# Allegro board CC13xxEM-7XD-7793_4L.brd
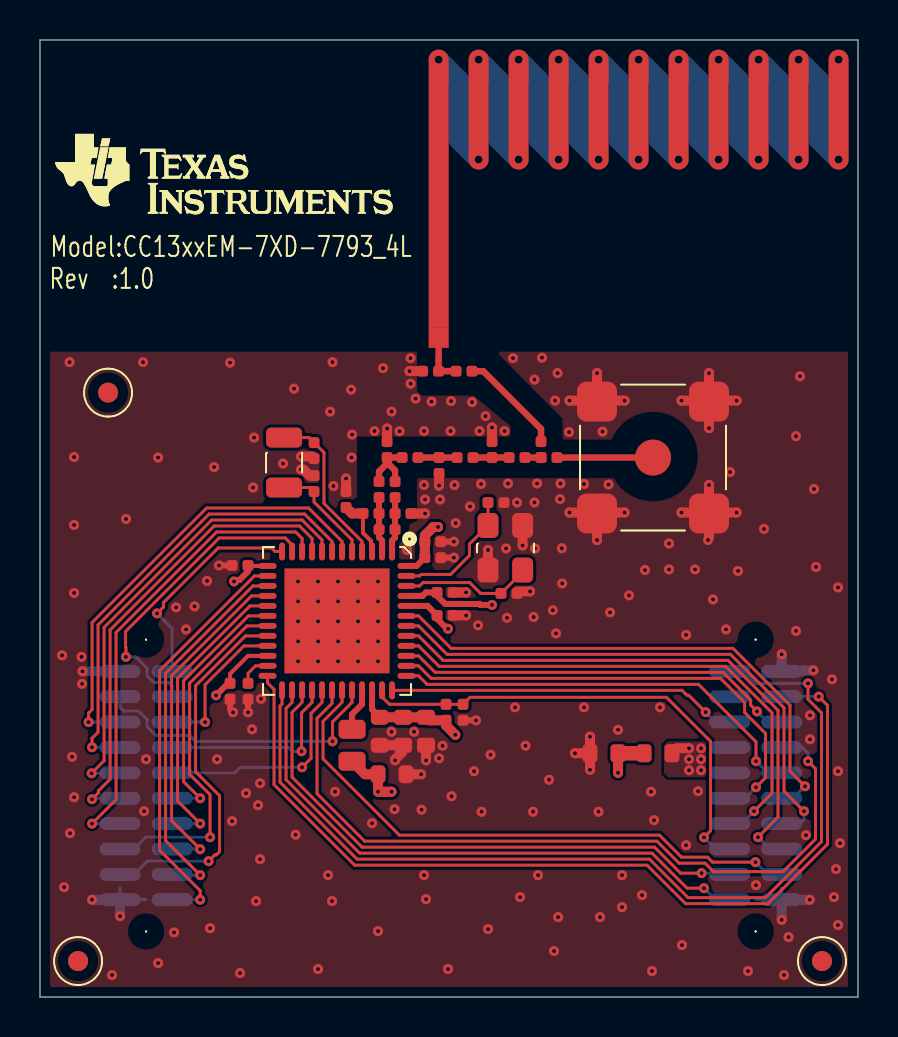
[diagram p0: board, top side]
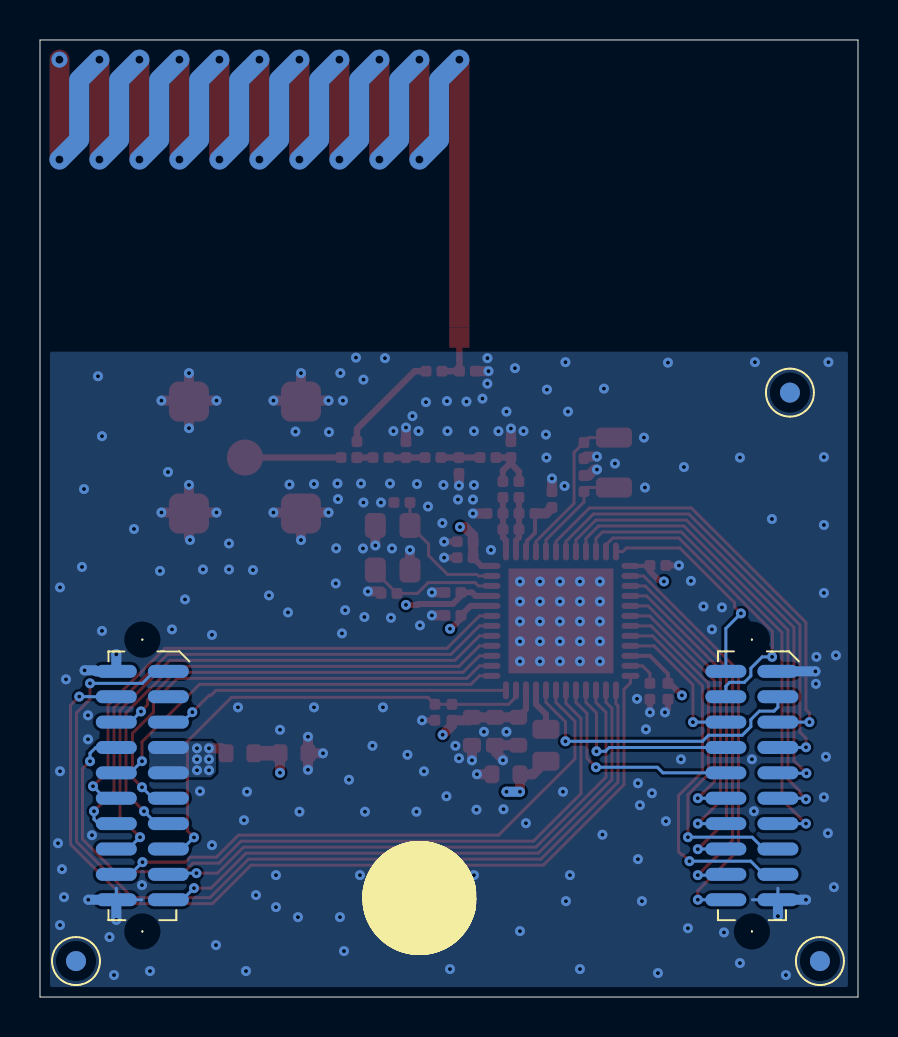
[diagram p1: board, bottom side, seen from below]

Outline 40.9 x 47.9 mm; copper layers: TOP, L2, L3, BOTTOM. Coordinates in mm from the lower left corner of the outline.
Outline path: 0,47.9 0,0 40.9,0 40.9,47.9 0,47.9

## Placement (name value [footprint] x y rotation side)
A1  Antenna PCB helix 868/915MHz  [ANTENNA868_915MHZ_A2N]  19.93 32.99 0 top
C1  DNM  [CAPC1608X90L]  28.9 12.2 180 top
C11  3.6pF  [CAPC1005X60L]  17.75 24.2 0 top
C12  2.7pF  [CAPC1005X60L]  17.35 27 90 top
C13  6.2pF  [CAPC1005X60L]  19.95 26.2 90 top
C14  3.3pF  [CAPC1005X60L]  22.6 27.8 270 top
C15  100pF  [CAPC1005X60L]  24.25 27 180 top
C21  100pF  [CAPC1005X60L]  15.3 25.3 270 top
C22  3.6pF  [CAPC1005X60L]  16.95 25 90 top
C41  12pF  [CAPC1005X60L]  13.7 27.75 270 top
C51  12pF  [CAPC1005X60L]  13.7 25.3 90 top
C131  100nF  [CAPC1005X60L]  10.4 21.6 180 top
C221  100nF  [CAPC1005X60L]  9.5 15.7 270 top
C231  1uF  [CAPC1005X60L]  10.4 15.7 270 top
C331  22uF  [CAPC1608X100A2L]  16.9 11.15 0 top
C341  22uF  [CAPC1608X100A2L]  16.99 14 270 top
C342  100nF  [CAPC1608X90L]  18.15 14 270 top
C343  NC  [CAPC1608X90L]  19.3 14 270 top
C351  100nF  [CAPC1005X60L]  21.15 14.65 270 top
C441  100nF  [CAPC1005X60L]  19.85 19.1 0 top
C451  100nF  [CAPC1005X60L]  19.85 20.25 0 top
C461  DNM  [CAPC1005X60L]  23.05 20.2 0 top
C471  DNM  [CAPC1005X60L]  22.4 24.75 0 top
C481  100nF  [CAPC1005X60L]  19.24 21.99 0 top
C482  DNM  [CAPC1005X60L]  19.24 22.79 0 top
FIDU1  FIDU_1MM  [FID100X115]  1.9 1.8 0 top
FIDU2  FIDU_1MM  [FID100X115]  39.1 1.8 0 top
FIDU3  FIDU_1MM  [FID100X115]  3.4 30.25 0 top
FIDU4  FIDU_1MM  [FID100X115]  1.9 1.8 180 bottom
FIDU5  FIDU_1MM  [FID100X115]  39.1 1.8 180 bottom
FIDU6  FIDU_1MM  [FID100X115]  3.4 30.25 180 bottom
FL1  BLM18HE152SN1  [FIL_BLM18HE152SN1DL]  30.2 12.2 0 top
J1  SMA-10V21-TGG  [HUSTSAN_SMA10V21TGGAN]  30.65 27 0 top
L11  18nH  [INDC1005X60L]  17.75 23.4 180 top
L12  7.5nH  [INDC1005X60A2L]  17.76 25 90 top
L13  6.8nH  [INDC1005X60L]  18.1 27 0 top
L14  6.8nH  [INDC1005X60L]  20.85 27 0 top
L15  TBD  [INDC1005X60L]  19.93 31.33 180 top
L21  7.5nH  [INDC1005X60A2L]  16.95 24.2 180 top
L331  6.8uH  [INDC2012X150L]  15.6 13.4 270 top
NOREF  -  []  0 40.78 0 top
NOREF#2  -  []  1.75 43.2 0 top
NOREF#3  -  []  32.36 0 90 top
NOREF#4  -  []  25.1 1.92 180 bottom
P1  SFM-110-02-S-D-A-K-TR  [SAMTEC_SFM11002AN]  4 16.3 0 bottom
P2  SFM-110-02-S-D-A-K-TR  [SAMTEC_SFM11002AN]  34.48 16.3 0 bottom
R11  0  [RESC1005X40L]  25.85 27 180 top
R12  DNM  [RESC1005X40L]  25.05 27 90 top
R13  0  [RESC1005X40L]  20.8 31.32 0 top
R351  100k  [RESC1005X40L]  20.3 14.65 270 top
U1  CC13xx 7x7  [QFNFC50P700X700X80-49CN]  17.6 22.3 180 top
Y1  32.768kHz  [XTAL_FC-135N]  12.2 28 270 top
Y2  24MHz  [OSCCC250X320X60-4L]  22.4 23.6 270 top

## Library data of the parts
A1 = ANTENNA: User Part Number: #PN
C1 C342 C343 = CAPACITOR: alternate symbols: (CAPC1608X90L,CAPC1608X90M)
C11-C15 C21 C22 C41 C51 C131 C221 C231 C351 C441 C451 C461 C471 C481 C482 = CAPACITOR: alternate symbols: (CAPC1005X60L,CAPC1005X60M)
C331 C341 = CAPACITOR: User Part Number: #PN; alternate symbols: (CAPC1608X100A2L,CAPC1608X100A2M)
FIDU1-FIDU6 = FIDMARK
FL1 = FILTER_2PIN: alternate symbols: (FIL_BLM18HE152SN1DL,FIL_BLM18HE152SN1DM)
J1 = CONN_COAX_1+4: alternate symbols: (HUSTSAN_SMA10V21TGGL,HUSTSAN_SMA10V21TGGM)
L11 L13 L14 = INDUCTOR: alternate symbols: (INDC1005X60L,INDC1005X60M)
L12 L21 = IND_HOR: User Part Number: #PN; alternate symbols: (INDC1005X60A2L,INDC1005X60A2M)
L15 = INDUCTOR: alternate symbols: (INDC1005X60M,INDC1005X60L)
L331 = INDUCTOR: alternate symbols: (INDC2012X150L,INDC2012X150M)
P1 P2 = CONN_HEADER_2X10_P_S
R11-R13 R351 = RESISTOR: alternate symbols: (RESC1005X40L,RESC1005X40M)
U1 = IC_RF_CC13XX_7X7_QFN48_V2: alternate symbols: (QFNFC50P700X700X80-49CL,QFNFC50P700X700X80-49CM)
Y1 = CRYSTAL: alternate symbols: (XTAL_FC-135L,XTAL_FC-135M)
Y2 = XTAL_4PIN_S: alternate symbols: (OSCCC250X320X60-4L,OSCCC250X320X60-4M)

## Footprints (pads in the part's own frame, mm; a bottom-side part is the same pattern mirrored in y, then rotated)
ANTENNA868_915MHZ_A2N
  rect 1x1 smd: 1(0,0)
CAPC1005X60L
  custom 0.135x0.135 smd: 1(0,0) 2(0.8,0)
CAPC1608X90L
  custom 0.188x0.188 smd: 1(0,0) 2(1.4,0)
CAPC1608X100A2L
  custom 0.188x0.188 smd: 1(0,0) 2(1.4,0)
FID100X115
  oval 1x1 smd: 1(0,0)
FIL_BLM18HE152SN1DL
  custom 0.188x0.188 smd: 1(0,0) 2(1.4,0)
HUSTSAN_SMA10V21TGGAN
  round 1.801 smd: 1(0,0)
  custom 0.5x0.5 smd: 2(-2.8,-2.8) 3(2.8,-2.8) 4(2.8,2.8) 5(-2.8,2.8)
INDC1005X60A2L
  custom 0.135x0.135 smd: 1(0,0) 2(0.8,0)
INDC1005X60L
  custom 0.135x0.135 smd: 1(0,0) 2(0.8,0)
INDC2012X150L
  custom 0.237x0.237 smd: 1(0,0) 2(1.6,0)
OSCCC250X320X60-4L
  custom 0.263x0.263 smd: 1(0,0) 2(2.23,0) 3(2.23,1.73) 4(0,1.73)
QFNFC50P700X700X80-49CN
  oval 0.3x0.9 smd: 1(0,0) 2(0.5,0) 3(1,0) 4(1.5,0) 5(2,0) 6(2.5,0) 7(3,0) 8(3.5,0) 9(4,0) 10(4.5,0) 11(5,0) 12(5.5,0) 25(5.5,6.95) 26(5,6.95) 27(4.5,6.95) 28(4,6.95) 29(3.5,6.95) 30(3,6.95) 31(2.5,6.95) 32(2,6.95) 33(1.5,6.95) 34(1,6.95) 35(0.5,6.95) 36(0,6.95)
  oval 0.9x0.3 smd: 13(6.225,0.725) 14(6.225,1.225) 15(6.225,1.725) 16(6.225,2.225) 17(6.225,2.725) 18(6.225,3.225) 19(6.225,3.725) 20(6.225,4.225) 21(6.225,4.725) 22(6.225,5.225) 23(6.225,5.725) 24(6.225,6.225) 37(-0.725,6.225) 38(-0.725,5.725) 39(-0.725,5.225) 40(-0.725,4.725) 41(-0.725,4.225) 42(-0.725,3.725) 43(-0.725,3.225) 44(-0.725,2.725) 45(-0.725,2.225) 46(-0.725,1.725) 47(-0.725,1.225) 48(-0.725,0.725)
  rect 5.25x5.25 smd: 49(2.75,3.475)
RESC1005X40L
  custom 0.135x0.135 smd: 1(0,0) 2(0.8,0)
SAMTEC_SFM11002AN
  round 0.099 hole 1.501 unplated: (1.302,-1.588) (1.302,13.017)
  oval 2.05x0.65 smd: 1(0,0) 2(2.604,0) 3(0,1.27) 4(2.604,1.27) 5(0,2.54) 6(2.604,2.54) 7(0,3.81) 8(2.604,3.81) 9(0,5.08) 10(2.604,5.08) 11(0,6.35) 12(2.604,6.35) 13(0,7.62) 14(2.604,7.62) 15(0,8.89) 16(2.604,8.89) 17(0,10.16) 18(2.604,10.16) 19(0,11.43) 20(2.604,11.43)
XTAL_FC-135N
  custom 0.25x0.25 smd: 1(0,0) 2(2.5,0)

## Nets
GND: C1.2 C11.2 C12.2 C13.1 C14.1 C21.1 C41.2 C51.2 C131.2 C221.2 C231.2 C331.2 C341.2 C342.2 C343.2 C351.2 C441.2 C451.2 C461.2 C471.2 C481.2 C482.2 J1.2 J1.3 J1.4 J1.5 L15.2 P1.1 P1.19 P2.2 P2.20 U1.49(VSS) Y2.2 Y2.4
VDD_EB: FL1.2 P2.7 P2.9
VDDR: C331.1 C451.1 C481.1 C482.1 L331.2 U1.45(VDDR#45) U1.48(VDDR#48)
VDDS: C1.1 C131.1 C221.1 C341.1 C342.1 C343.1 C441.1 FL1.1 R351.2 U1.13(VDDS2) U1.22(VDDS3) U1.34(VDDS_DCDC) U1.44(VDDS)
DCDC_SW: L331.1 U1.33(DCDC_SW)
DIO_1: P1.5 U1.6(DIO_1)
DIO_2: P1.7 U1.7(DIO_2)
DIO_3: P1.9 U1.8(DIO_3)
DIO_4: P1.11 U1.9(DIO_4)
DIO_5: P1.13 U1.10(DIO_5)
DIO_6: P1.4 U1.11(DIO_6)
DIO_7: P1.2 U1.12(DIO_7)
DIO_8: P1.20 U1.14(DIO_8)
DIO_9: P1.18 U1.15(DIO_9)
DIO_10: P1.16 U1.16(DIO_10)
DIO_11: P1.14 U1.17(DIO_11)
DIO_12: P1.12 U1.18(DIO_12)
DIO_13: P1.15 U1.19(DIO_13)
DIO_14: P1.17 U1.20(DIO_14)
DIO_15: P1.6 U1.21(DIO_15)
DIO_16 / JTAG TDO: P2.19 U1.26(DIO_16)
DIO_17 / JTAG TDI: P2.17 U1.27(DIO_17)
DIO_18: P1.8 U1.28(DIO_18)
DIO_19: P1.10 U1.29(DIO_19)
DIO_20: P2.8 U1.30(DIO_20)
DIO_21: P2.18 U1.31(DIO_21)
DIO_22: P1.3 U1.32(DIO_22)
DIO_23: P2.5 U1.36(DIO_23)
DIO_24: P2.10 U1.37(DIO_24)
DIO_25: P2.11 U1.38(DIO_25)
DIO_26: P2.6 U1.39(DIO_26)
DIO_27: P2.13 U1.40(DIO_27)
DIO_28: P2.16 U1.41(DIO_28)
DIO_29: P2.14 U1.42(DIO_29)
DIO_30: P2.12 U1.43(DIO_30)
JTAG_TCK: P2.1 U1.25(JTAG_TCKC)
JTAG_TMS: P2.4 U1.24(JTAG_TMSC)
NRESET: C351.1 P2.15 R351.1 U1.35(RESET_N)
N485531: J1.1 R11.1
N485535: A1.1(FEED/GND_1) L15.1 R13.1
N485571: C461.1 U1.46(X24M_N) Y2.3
N485643: C22.1 L11.2 L21.1 U1.2(RF_N)
N485645: C11.1 L11.1 L12.1 U1.1(RF_P)
N485661: C12.1 C22.2 L12.2 L13.1
N485675: C13.2 L13.2 L14.1
N485699: C231.1 U1.23(DCOUPL)
N485701: C41.1 U1.4(X32K_Q1) Y1.1
N485707: C51.1 U1.5(X32K_Q2) Y1.2
N485827: C14.2 C15.2 L14.2
N485893: C15.1 R11.2 R12.1
N485901: R12.2 R13.2
N485927: C21.2 L21.2 U1.3(RX_TX)
N485953: C471.1 U1.47(X24M_P) Y2.1

Pads without a net: FIDU1 1; FIDU2 1; FIDU3 1; FIDU4 1; FIDU5 1; FIDU6 1; P2 3

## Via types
v1: diameter 0.5, hole 0.2, TOP to BOTTOM, 286 vias
v2: diameter 0.8, hole 0.4, TOP to BOTTOM, 21 vias

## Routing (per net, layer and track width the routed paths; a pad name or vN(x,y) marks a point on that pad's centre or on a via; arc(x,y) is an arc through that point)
GND: length 51.4
  TOP w0.15: v1(14.9,18.8) 14.88,18.83 U1.49
  TOP w0.3: C131.2 v1(8.95,21.6) ; v1(20.7,22.79) C482.2 ; C221.2 9.5,14.4 9.65,14.25 v1(9.65,14.25) ; v1(20.7,21.99) C481.2 ; v1(10.4,14.25) C231.2 ; C351.2 v1(21.8,13.85)
  TOP w0.5: C11.2 v1(19.26,24.2) ; C1.2 v1(27.5,13.03) ; C1.2 v1(26.75,12.2) ; C1.2 v1(27.5,11.37) ; v1(34.83,29.85) 33.45,29.85 ; 33.45,29.85 J1.4 v1(33.45,28.47) ; 33.45,29.85 v1(32.08,29.85) ; 33.45,29.85 v1(33.45,31.23) ; 33.45,24.25 v1(32.08,24.25) ; 33.45,24.25 v1(34.83,24.25) ; 33.45,24.25 v1(33.45,25.63) ; 33.45,24.25 J1.3 33.45,23 ; L15.2 v1(18.48,31.33) ; C12.2 17.35,28.45 v1(17.36,28.45) ; v1(19.3,11.85) C343.2 ; 22.4,21.47 v1(22.4,22.37) ; v1(13.06,27.05) 13.6,27.05 C41.2 ; C441.2 v1(21.31,19.1) ; v1(27.85,22.87) J1.2 27.85,24.25 ; v1(17.75,11.85) 17.75,11.9 18.1,12.25 18.1,12.4 18.15,12.45 C342.2 17.1,12.6 ; v1(13.05,26.4) 13.18,26.4 13.48,26.1 C51.2 ; v1(24.13,22.6) Y2.4 24.13,23.7 ; C14.1 v1(22.6,28.5) ; 23.85,20.3 v1(24.51,20.3) ; C13.1 v1(19.95,25.6) ; 27.85,29.85 v1(26.48,29.85) ; 27.85,29.85 v1(27.85,31.23) ; 27.85,29.85 v1(29.23,29.85) ; 27.85,24.25 v1(26.48,24.25) ; 27.85,24.25 v1(29.23,24.25) ; C21.1 v1(15.3,25.95) ; C451.2 v1(21.31,20.25) ; C331.2 v1(19.06,11.15)
  BOTTOM w0.15: 38.08,16.3 38.36,16.3 ; 37.09,5.45 P2.20 35.81,4.87 ; 5.28,4.87 P1.19 4,5.45
  BOTTOM w0.5: v1(37.09,3.87) P2.20 v1(38.49,4.87) ; v1(4,4.05) P1.19 v1(2.6,4.87) ; v1(37.09,17.15) P2.2 38.08,16.3 38.13,16.35 v1(38.67,16.35) ; P1.1 v1(2.13,16.3)
  vias: v1(1.1,17.1) v1(1.2,5.5) v1(1.48,31.77) v1(1.5,8.2) v1(1.6,12.02) v1(1.7,27.02) v1(1.7,23.62) v1(1.7,20.22) v1(1.7,10) v1(2.08,17.02) v1(2.1,15.67) v1(3.6,1.1) v1(4.3,23.92) v1(5.15,31.77) v1(5.2,9.3) v1(5.3,11.9) v1(5.9,27) v1(5.9,1.7) v1(6.7,3.23) v1(6.8,19.5) v1(7.3,18.4) v1(7.73,19.55) v1(8.35,20.83) v1(8.5,3.44) v1(8.7,26.52) v1(8.85,11.9) v1(9.5,31.75) v1(9.6,8.8) v1(10,1.2) v1(10.3,10.2) v1(10.6,13.4) v1(10.7,28) v1(10.65,25.5) v1(10.8,4.8) v1(10.9,9.6) v1(11.05,14.92) v1(11,10.7) v1(11,6.9) v1(12.15,26.7) v1(12.7,30.45) v1(12.78,8.12) v1(12.9,20.8) v1(12.9,19.8) v1(12.9,18.8) v1(12.9,17.8) v1(12.9,16.8) v1(13.9,20.8) v1(13.9,19.8) v1(13.9,18.8) v1(13.9,17.8) v1(13.9,16.8) v1(13.9,1.4) v1(14.4,6.1) v1(14.5,29.3) v1(14.63,31.77) v1(14.6,4.8) v1(14.67,25.58) v1(14.75,10.27) v1(14.9,20.8) v1(14.9,19.8) v1(14.9,17.8) v1(14.9,16.8) v1(15.55,30.4) v1(15.6,28.15) v1(15.58,27) v1(15.9,20.8) v1(15.9,19.8) v1(15.9,18.8) v1(15.9,17.8) v1(15.9,16.8) v1(16.6,8.7) v1(16.73,28.33) v1(16.9,20.8) v1(16.9,19.8) v1(16.9,18.8) v1(16.9,17.8) v1(16.9,16.8) v1(16.9,3.3) v1(17.15,31.47) v1(17.58,29.3) v1(17.58,13.27) v1(17.73,9.4) v1(17.98,28.32) v1(18.35,22.38) v1(18.53,31.97) v1(18.53,30.7) v1(18.7,13.27) v1(18.78,29.95) v1(19.08,9.38) v1(19.2,28.33) v1(19.2,25.62) v1(19.25,24.9) v1(19.2,6.1) v1(19.3,4.9) v1(19.58,29.8) v1(20,24.9) v1(19.95,11.95) v1(20.13,12.58) v1(20.4,1.4) v1(20.55,29.83) v1(20.53,28.33) v1(20.58,10.05) v1(20.73,25.62) v1(20.78,23.72) v1(21.5,24.55) v1(21.6,29.77) v1(21.7,11.3) v1(21.9,18.6) v1(21.98,28.33) v1(22.05,25.67) v1(22.08,9.27) v1(22.28,29.08) v1(22.4,3.4) v1(22.53,12.12) v1(23.23,28.33) v1(23.3,22.45) v1(23.35,18.98) v1(23.4,25.7) v1(23.65,31.97) v1(23.75,14.5) v1(23.86,24.75) v1(24,5) v1(24.28,12.58) v1(24.73,30.9) v1(24.73,24.75) v1(24.68,19.02) v1(24.65,9.27) v1(24.85,25.7) v1(24.75,22.45) v1(24.9,6.1) v1(25.1,32) v1(25.45,10.88) v1(25.64,19.36) v1(25.7,2.3) v1(25.75,29.85) v1(25.8,18.2) v1(25.88,31.23) v1(25.9,4) v1(26.03,25.7) v1(26,24.92) v1(26.09,22.46) v1(26.11,20.7) v1(26.45,28.27) v1(27.2,25.67) v1(27.2,14.5) v1(27.93,9.27) v1(28,4) v1(28.13,28.3) v1(28.43,25.65) v1(28.5,19.25) v1(28.9,13.38) v1(29.1,6.1) v1(29.1,4.5) v1(29.45,20.1) v1(30.1,5.1) v1(30.25,21.37) v1(30.55,10.27) v1(30.6,1.3) v1(30.7,8.85) v1(31,14.5) v1(31.45,22.7) v1(31.45,21.4) v1(32.1,2.6) v1(32.3,18.12) v1(32.3,7.6) v1(32.75,21.4) v1(32.9,10.3) v1(33.4,22.87) v1(33.65,19.9) v1(34.3,18.4) v1(34.5,26.27) v1(34.9,21.33) v1(35.4,1.3) v1(35.8,5.6) v1(36.2,23.42) v1(37.2,1.1) v1(37.43,3) v1(37.8,28.07) v1(37.8,18.33) v1(38,31.07) v1(38.3,8.1) v1(38.5,14.1) v1(38.5,12.9) v1(38.7,25.42) v1(38.8,21.52) v1(39.6,15.9) v1(39.7,5) v1(39.8,6.4) v1(39.9,20.5) v1(39.9,11.3) v1(39.9,3.6) v1(40,7.7)
VDD_EB: length 1
  TOP w0.5: FL1.2 31.85,12.45 v1(32.45,12.45)
  vias: v1(32.45,11.9) v1(32.45,11.35) v1(33.05,12.45) v1(33.05,11.9) v1(33.05,11.35)
VDDR: length 30.7
  TOP w0.3: U1.45 19.13,20.08 19.3,20.25 C451.1 19.85,20.08 20.26,19.67 21.98,19.67 ; v1(22.6,19.62) 22.03,19.62 ; U1.48 18.83,21.58 C481.1
  TOP w0.32: 22.03,19.62 21.98,19.67
  TOP w0.5: v1(19.9,23.52) 19.67,23.52 19.24,23.1 C482.1 C481.1 ; L331.2 16.25,11.15 C331.1 v1(16.9,10.27) v1(17.58,10.27)
  L2 w0.5: v1(16.9,10.27) v1(17.58,10.27)
  L3 w0.5: v1(19.9,23.52) 19.9,21.86 20.43,21.34 21.14,21.34 22.6,19.87 v1(22.6,19.62) 22.6,13.64 19.23,10.27 v1(17.58,10.27) v1(16.9,10.27)
  BOTTOM w0.5: v1(16.9,10.27) v1(17.58,10.27)
VDDS: length 65.9
  TOP w0.2: C131.1 10.43,21.58 U1.13 ; C221.1 9.5,16.18 10.4,17.08 U1.22
  TOP w0.3: U1.34 16.6,14.4 16.99,14.01 C341.1 ; v1(20.4,18.43) 20.28,18.55 20.23,18.55 19.85,18.93 C441.1 19.38,19.58 U1.44 ; C221.1 9.41,15.7 v1(8.8,15.1) ; C131.1 10.4,21.3 9.98,20.87 9.78,20.87 v1(9.7,20.8)
  TOP w0.5: v1(28.9,11.22) C1.1 ; C341.1 18.15,14 C342.1 C343.1 19.45,13.85 R351.2 20.3,13.59 v1(20.77,13.12)
  TOP w0.73: FL1.1 C1.1
  L3 w0.5: 16.41,14.44 v1(20.4,18.43) ; 16.41,14.44 15.95,13.98 15.95,7.98 ; 16.41,14.44 19.45,14.44 v1(20.77,13.12) ; 15.95,7.98 15,7.98 8.8,14.18 v1(8.8,15.1) 8.8,19.9 v1(9.7,20.8) ; 15.95,7.98 27.55,7.98 28.9,9.33 v1(28.9,11.22)
DCDC_SW: length 2.2
  TOP w0.3: U1.33 16.1,14.65 15.6,14.15 L331.1
DIO_1: length 22.7
  TOP w0.15: U1.6 15.1,22.8 13.43,24.47 8.33,24.47 2.6,18.75 2.6,14.39 2.43,14.21 v1(2.43,13.76)
  BOTTOM w0.15: v1(2.43,13.76) P1.5
DIO_2: length 22.7
  TOP w0.15: U1.7 14.6,22.8 13.23,24.17 8.46,24.17 2.9,18.62 2.9,13.25 2.6,12.95 v1(2.6,12.5)
  BOTTOM w0.15: v1(2.6,12.5) 2.8,12.5 2.81,12.49 P1.7
DIO_3: length 23.1
  TOP w0.15: U1.8 14.1,22.88 13.1,23.88 8.58,23.88 3.2,18.5 3.2,11.83 v1(2.58,11.2)
  BOTTOM w0.15: P1.9 3.98,11.2 v1(2.58,11.2)
DIO_4: length 23.4
  TOP w0.15: v1(2.6,9.9) 2.92,10.22 2.92,10.32 3.5,10.9 3.5,18.37 8.71,23.58 12.98,23.58 13.6,22.95 U1.9
  BOTTOM w0.15: P1.11 2.7,9.95 2.65,9.9 v1(2.6,9.9)
DIO_5: length 23.6
  TOP w0.15: U1.10 13.1,22.95 12.78,23.27 8.83,23.27 3.8,18.25 3.8,9.88 v1(2.6,8.68)
  BOTTOM w0.15: P1.13 v1(2.6,8.68)
DIO_6: length 15.7
  TOP w0.15: v1(4.3,17.02) 4.3,17.48 4.28,17.49 4.28,18.3 8.96,22.97 12.26,22.97 12.6,22.63 U1.11
  BOTTOM w0.15: v1(4.3,17.02) 4.79,17.02 5.36,16.46 5.36,16.07 5.68,15.75 6.42,15.75 6.61,15.56 P1.4
DIO_7: length 11
  TOP w0.15: v1(5.85,19.2) 6.17,19.52 6.17,19.74 8.91,22.47 11.58,22.47 11.75,22.3 U1.12
  BOTTOM w0.15: P1.2 6.61,18.45 v1(5.85,19.2)
DIO_8: length 21.1
  TOP w0.15: U1.14 10.72,21.08 5.98,16.33 5.98,7.35 8.01,5.32 v1(8.01,4.87)
  BOTTOM w0.15: P1.20 v1(8.01,4.87)
DIO_9: length 19.2
  TOP w0.15: v1(8.01,6.1) 6.28,7.83 6.28,16.21 10.65,20.58 U1.15
  BOTTOM w0.15: v1(8.01,6.1) 6.65,6.1 P1.18
DIO_10: length 17.1
  TOP w0.15: v1(8.01,7.4) 6.58,8.83 6.58,16.08 10.57,20.08 U1.16
  BOTTOM w0.15: P1.16 7.84,7.41 7.84,7.4 v1(8.01,7.4)
DIO_11: length 15.1
  TOP w0.15: U1.17 10.5,19.58 6.88,15.96 6.88,9.81 v1(8.01,8.68)
  BOTTOM w0.15: v1(8.01,8.68) P1.14
DIO_12: length 13.2
  TOP w0.15: U1.18 10.42,19.08 7.18,15.83 7.18,10.78 v1(8.01,9.95)
  BOTTOM w0.15: v1(8.01,9.95) P1.12
DIO_13: length 18
  TOP w0.15: U1.19 10.35,18.58 7.48,15.7 7.48,11.15 8.5,10.13 v1(8.5,8)
  BOTTOM w0.15: v1(8.5,8) 5.29,8 4.7,7.41 P1.15
DIO_14: length 18.9
  TOP w0.15: v1(8.43,6.8) 8.75,7.12 8.82,7.12 8.98,7.27 8.98,10.08 7.78,11.28 7.78,15.58 10.27,18.08 U1.20
  BOTTOM w0.15: P1.17 4.7,6.14 5.36,6.8 v1(8.43,6.8)
DIO_15: length 7.4
  TOP w0.15: U1.21 10.2,17.58 8.25,15.63 v1(8.25,13.76)
  BOTTOM w0.15: P1.6 v1(8.25,13.76)
DIO_16 / JTAG TDO: length 29.3
  TOP w0.15: v1(33.2,5.45) 32.35,5.45 30.6,7.2 15.98,7.2 12.3,10.88 12.3,14.45 12.6,14.75 U1.26
  BOTTOM w0.15: v1(33.2,5.45) 33.78,4.87 P2.19
DIO_17 / JTAG TDI: length 28.4
  TOP w0.15: v1(33.08,6.2) 32.03,6.2 30.73,7.5 16.11,7.5 12.6,11 12.6,14.25 13.1,14.75 U1.27
  BOTTOM w0.15: P2.17 33.78,6.14 33.72,6.2 v1(33.08,6.2)
DIO_18: length 9.8
  TOP w0.15: U1.28 13.6,14.75 13.08,14.22 v1(13.08,12.3)
  BOTTOM w0.15: v1(13.08,12.3) 12.63,12.3 12.44,12.49 P1.8
DIO_19: length 10.9
  TOP w0.15: v1(13.1,11.5) 13.55,11.95 13.55,14.2 14.1,14.75 U1.29
  BOTTOM w0.15: v1(13.1,11.5) 10.03,11.5 9.75,11.22 P1.10
DIO_20: length 38.6
  TOP w0.15: v1(38.4,11.8) 38.78,11.42 38.78,7.9 37.15,6.27 33.68,6.27 33.25,6.7 31.95,6.7 30.85,7.8 16.23,7.8 13.85,10.18 13.85,13.95 14.6,14.7 U1.30
  BOTTOM w0.15: P2.8 38.11,12.49 38.4,12.2 v1(38.4,11.8)
DIO_21: length 29.2
  TOP w0.15: v1(35.78,6.75) 33.63,6.75 33.38,7 32.08,7 30.98,8.1 17.97,8.1 14.15,11.92 14.15,13.8 15.1,14.75 U1.31
  BOTTOM w0.15: P2.18 36.39,6.14 v1(35.78,6.75)
DIO_22: length 15
  TOP w0.15: v1(14.63,12.8) 14.63,13.77 15.6,14.75 U1.32
  BOTTOM w0.15: v1(14.63,12.8) 7.78,12.8 7.48,13.1 5.79,13.1 5.36,13.53 5.36,13.88 4.93,14.31 4.2,14.31 4,14.5 P1.3
DIO_23: length 17.5
  TOP w0.15: v1(33.29,14.26) 32.44,15.1 32.35,15.1 32.1,15.35 U1.36
  BOTTOM w0.15: P2.5 33.78,13.76 v1(33.29,14.26)
DIO_24: length 21.3
  TOP w0.15: U1.37 18.93,16.08 19.36,15.65 32.93,15.65 35.8,12.77 v1(35.8,11.8)
  BOTTOM w0.15: P2.10 36.39,11.22 v1(35.8,11.8)
DIO_25: length 24.1
  TOP w0.15: v1(35.8,10.5) 36.28,10.97 36.28,13.2 35.23,14.24 35.23,14.74 34.03,15.95 19.56,15.95 18.93,16.58 U1.38
  BOTTOM w0.15: P2.11 35.25,9.95 v1(35.8,10.5)
DIO_26: length 20.3
  TOP w0.15: U1.39 18.93,17.08 19.76,16.25 34.15,16.25 35.53,14.87 35.53,14.61 v1(35.85,14.29)
  BOTTOM w0.15: v1(35.85,14.29) 36.39,13.76 P2.6
DIO_27: length 26.4
  TOP w0.15: U1.40 18.93,17.58 19.96,16.55 34.28,16.55 36.6,14.22 36.6,10.2 v1(35.7,9.3)
  BOTTOM w0.15: v1(35.7,9.3) 35.08,8.68 P2.13
DIO_28: length 28.3
  TOP w0.15: U1.41 18.93,18.08 20.16,16.85 34.4,16.85 36.9,14.35 36.9,9 v1(35.9,8)
  BOTTOM w0.15: v1(35.9,8) 36.5,7.4 37.08,7.4 P2.16
DIO_29: length 27.8
  TOP w0.15: v1(38.2,9.3) 37.2,10.3 37.2,14.47 34.53,17.15 20.36,17.15 18.93,18.58 U1.42
  BOTTOM w0.15: v1(38.2,9.3) 38.2,8.9 37.98,8.68 P2.14
DIO_30: length 26.8
  TOP w0.15: U1.43 18.93,19.08 20.56,17.45 34.65,17.45 37.5,14.6 37.5,11.3 v1(38.25,10.55)
  BOTTOM w0.15: v1(38.25,10.55) 37.65,9.95 P2.12
JTAG_TCK: length 47.6
  TOP w0.15: U1.25 12.1,14.67 12,14.57 12,10.75 15.86,6.9 30.48,6.9 32.4,4.97 36.28,4.97 39.08,7.78 39.08,14.22 38.4,14.9 v1(38.4,15.7)
  BOTTOM w0.15: v1(38.4,15.7) 35.78,15.7 35.18,16.3 P2.1
JTAG_TMS: length 46.4
  TOP w0.15: U1.24 11.38,15.72 11.7,15.4 11.7,10.63 15.73,6.6 30.35,6.6 32.28,4.67 36.4,4.67 39.38,7.65 39.38,14.6 v1(38.94,15.04)
  BOTTOM w0.15: v1(38.94,15.04) 38.49,15.04 38.48,15.03 P2.4
Net_62:
  vias: v2(19.93,46.92) v2(21.93,41.92)
Net_63:
  vias: v2(37.93,46.92) v2(39.93,46.92) v2(39.93,41.92)
Net_64:
  vias: v2(35.93,46.92) v2(37.93,41.92)
Net_65:
  vias: v2(33.93,46.92) v2(35.93,41.92)
Net_66:
  vias: v2(31.93,46.92) v2(33.93,41.92)
Net_67:
  vias: v2(29.93,46.92) v2(31.93,41.92)
Net_68:
  vias: v2(27.93,46.92) v2(29.93,41.92)
Net_69:
  vias: v2(25.93,46.92) v2(27.93,41.92)
Net_70:
  vias: v2(23.93,46.92) v2(25.93,41.92)
Net_71:
  vias: v2(21.93,46.92) v2(23.93,41.92)
NRESET: length 24.4
  TOP w0.15: U1.35 17.1,15.02 17.47,14.65 R351.1 C351.1 21.5,15 31.33,15 33.53,12.8 33.53,8.31 v1(33.2,7.99)
  BOTTOM w0.15: v1(33.2,7.99) 33.78,7.41 P2.15
N485531: length 4.8
  TOP w0.32: R11.1 J1.1
N485535: length 2.5
  TOP w0.32: R13.1 20.8,31.33 L15.1 19.93,31.88 19.93,31.89 A1.1
N485571: length 6.6
  TOP w0.15: Y2.3 24.13,21.28 C461.1 22.03,20.2 21.49,20.74 19.15,20.74 18.98,20.58 U1.46
N485643: length 2.8
  TOP w0.3: U1.2 17.1,22.85 16.95,23 L11.2 16.95,24.2 L21.1 16.95,25 C22.1
N485645: length 2.8
  TOP w0.3: L12.1 17.76,24.2 C11.1 L11.1 17.75,23 17.6,22.85 U1.1
N485661: length 3.2
  TOP w0.3: L12.2 17.76,26.35 17.75,26.35 ; 17.35,26.75 C12.1
  TOP w0.32: C22.2 16.95,26.3 17.35,26.7 17.35,26.75 17.75,26.35 ; C12.1 L13.1
N485675: length 1.9
  TOP w0.32: L13.2 C13.2 L14.1
N485699: length 1.6
  TOP w0.15: C231.1 10.4,16.2 10.78,16.58 U1.23
N485701: length 8
  TOP w0.15: Y1.1 13.45,28 C41.1 14.2,27.25 14.2,24.7 16.1,22.8 U1.4
N485707: length 5.4
  TOP w0.15: U1.5 15.6,22.88 13.7,24.77 C51.1 13.5,25.5 Y1.2
N485827: length 1.8
  TOP w0.32: L14.2 C14.2 C15.2
N485893: length 0.8
  TOP w0.32: C15.1 R11.2
N485901: length 5.3
  TOP w0.32: R13.2 22.17,31.32 25.05,28.44 R12.2
N485927: length 3.1
  TOP w0.2: U1.3 16.55,22.35 16.55,22.83 16.15,23.23 L21.2
  TOP w0.5: C21.2 15.6,24.2 L21.2
N485953: length 6.6
  TOP w0.15: U1.47 18.98,21.08 19.06,21.15 20.53,21.15 21.47,22.1 21.47,22.67 Y2.1 C471.1

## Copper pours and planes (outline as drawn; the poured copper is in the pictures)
GND on TOP: 18.85,23.9 18.45,23.61 18.45,23.09 17.95,22.69 17.95,21.97 18.01,21.9 18.75,21.9 18.75,23.2 19.28,23.72
GND on TOP: 0.5,0.5 0.5,32.3 18.85,32.3 18.85,30.35 19.1,30.1 21.68,30.1 23.53,28.58 23.53,28.05 15.85,28.05 15.85,23.2 16.35,22.7 17.9,22.7 17.9,22.2 11.5,22.2 11.5,15.5 18.2,15.5 18.2,21.6 19.2,21.6 19.2,23.2 19.08,23.2 18.85,23.7 18.85,25.97 28.69,25.97 32.89,27.17 28.59,27.91 28.58,27.9 26.13,27.9 26.13,28.95 22.8,32.3 40.4,32.3 40.4,0.5 ; 5 cut-outs
GND on BOTTOM: 0.5,0.5 0.5,32.3 40.4,32.3 40.4,0.5 ; 8 cut-outs
GND on L2, L3: 0.5,0.5 0.5,32.3 40.4,32.3 40.4,0.5
VDD_EB on TOP: 31.4,12.8 33.2,12.8 33.4,12.6 33.4,11.2 33.2,11 31.4,11 31.2,11.2 31.2,12.6
VDD_EB on BOTTOM: 32.3,12.8 35.2,12.8 35.45,12.55 35.45,11.15 35.3,11 32.35,11 32.1,11.25 32.1,12.6
Net_62 on BOTTOM (solid shape): 19.58,46.56 19.58,47.27 20.29,47.27 21.3,46.26 21.41,46.09 21.45,45.9 21.45,43.11 22.29,42.27 22.29,41.56 21.58,41.56 20.59,42.55 20.49,42.71 20.45,42.9 20.45,45.69
Net_63 on BOTTOM (solid shape): 37.58,46.56 37.58,47.27 38.29,47.27 39.3,46.26 39.41,46.09 39.45,45.9 39.45,43.11 40.29,42.27 40.29,41.56 39.58,41.56 38.59,42.55 38.48,42.71 38.45,42.9 38.45,45.69
Net_64 on BOTTOM (solid shape): 35.58,46.56 35.58,47.27 36.29,47.27 37.3,46.26 37.41,46.09 37.45,45.9 37.45,43.11 38.29,42.27 38.29,41.56 37.58,41.56 36.59,42.55 36.48,42.71 36.45,42.9 36.45,45.69
Net_65 on BOTTOM (solid shape): 33.58,46.56 33.58,47.27 34.29,47.27 35.3,46.26 35.41,46.09 35.45,45.9 35.45,43.11 36.28,42.27 36.28,41.56 35.58,41.56 34.59,42.55 34.48,42.71 34.45,42.9 34.45,45.69
Net_66 on BOTTOM (solid shape): 31.58,46.56 31.58,47.27 32.29,47.27 33.3,46.26 33.41,46.09 33.45,45.9 33.45,43.11 34.29,42.27 34.29,41.56 33.58,41.56 32.59,42.55 32.48,42.71 32.45,42.9 32.45,45.69
Net_67 on BOTTOM (solid shape): 29.58,46.56 29.58,47.27 30.29,47.27 31.3,46.26 31.41,46.09 31.45,45.9 31.45,43.11 32.28,42.27 32.28,41.56 31.58,41.56 30.59,42.55 30.48,42.71 30.45,42.9 30.45,45.69
Net_68 on BOTTOM (solid shape): 27.58,46.56 27.58,47.27 28.29,47.27 29.3,46.26 29.41,46.09 29.45,45.9 29.45,43.11 30.29,42.27 30.28,41.56 29.58,41.56 28.59,42.55 28.48,42.71 28.45,42.9 28.45,45.69
Net_69 on BOTTOM (solid shape): 25.58,46.56 25.58,47.27 26.29,47.27 27.3,46.26 27.41,46.09 27.45,45.9 27.45,43.11 28.29,42.27 28.29,41.56 27.58,41.56 26.59,42.55 26.48,42.71 26.45,42.9 26.45,45.69
Net_70 on BOTTOM (solid shape): 23.58,46.56 23.58,47.27 24.29,47.27 25.3,46.26 25.41,46.09 25.45,45.9 25.45,43.11 26.28,42.27 26.28,41.56 25.58,41.56 24.59,42.55 24.48,42.71 24.45,42.9 24.45,45.69
Net_71 on BOTTOM (solid shape): 21.58,46.56 21.58,47.27 22.29,47.27 23.3,46.26 23.41,46.09 23.45,45.9 23.45,43.11 24.29,42.27 24.29,41.56 23.58,41.56 22.59,42.55 22.48,42.71 22.45,42.9 22.45,45.69

Small or netless copper shapes (teardrops, artwork), in the pictures only: 11 on TOP

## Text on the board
Ref Des/Silkscreen Top: Rev  :1.0 | Model:CC13xxEM-7XD-7793_4L
XSECTION_CHART: *  SURFACE - AIR 0 MM | L1: TOP CONDUCTOR - COPPER 0.035 MM | *  DIELECTRIC - FR-4 0.175 MM | L2: L2 PLANE - COPPER 0.018 MM | *  DIELECTRIC - FR-4 1.14 MM | L3: L3 PLANE - COPPER 0.018 MM | L4: BOTTOM CONDUCTOR - COPPER 0.035 MM | DESIGN CROSS SECTION CHART | ___________________________ | TOTAL THICKNESS 1.596 MM
DIMENSION: FIGURE | SIZE | 0.2 | 0.4 | 1.501 | DRILL CHART: TOP to BOTTOM | ALL UNITS ARE IN MILLIMETERS | PLATED | NON-PLATED | QTY | 261 | 25 | 21 | 4
